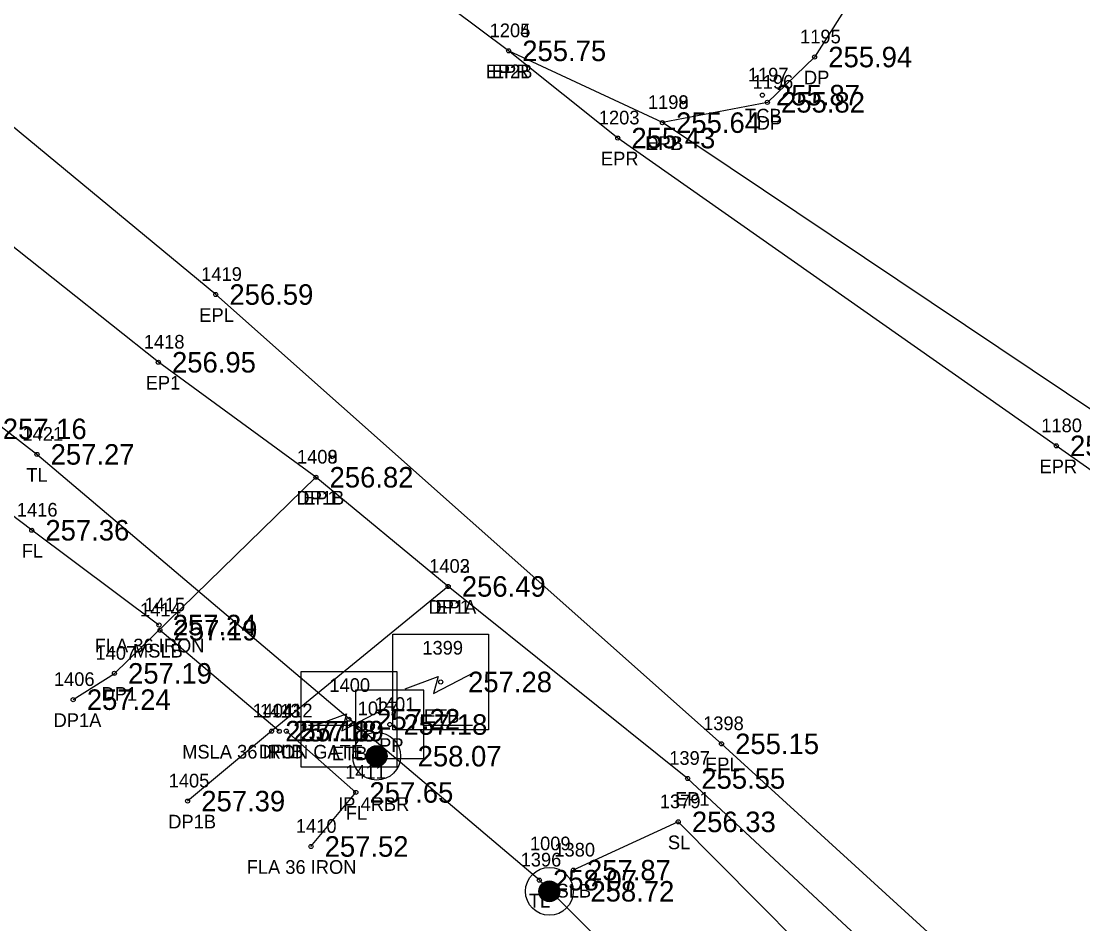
# Model space of a CAD drawing. Extents: x 1961231 to 1962574, y 799865 to 801120.
# Drawn here: x 1961948.3 to 1962025.9, y 800506.1 to 800572.1 of the extents above; entities that cross this region are included whole.
import ezdxf

# ---------------------------------------------------------------- set-up
doc = ezdxf.new("R2010")
doc.units = 0
for name, color, linetype in [('RD_EX_Conc_txCode', 7, 'Continuous'), ('RD_EX_Driveway', 7, 'Continuous'), ('RD_EX_Driveway_txCode', 7, 'Continuous'), ('RD_EX_DV_Prop_txCode', 7, 'Continuous'), ('RD_EX_DV_PropPin', 7, 'Continuous'), ('RD_EX_Fence_Other', 7, 'Continuous'), ('RD_EX_Fence_Other_txCode', 7, 'Continuous'), ('RD_EX_Misc', 7, 'Continuous'), ('RD_EX_Misc_txCode', 7, 'Continuous'), ('RD_EX_Road', 7, 'Continuous'), ('RD_EX_Road_txCode', 7, 'Continuous'), ('RD_EX_TX_Conc_ELEV', 7, 'Continuous'), ('RD_EX_TX_Driveway_ELEV', 7, 'Continuous'), ('RD_EX_TX_DV_Prop_ELEV', 7, 'Continuous'), ('RD_EX_TX_Fence_Other_ELEV', 7, 'Continuous'), ('RD_EX_TX_Misc_ELEV', 7, 'Continuous'), ('RD_EX_TX_Road_ELEV', 7, 'Continuous'), ('RD_EX_TX_UT_ELEV', 7, 'Continuous'), ('RD_EX_TX_VEG_ELEV', 7, 'Continuous'), ('RD_EX_UT', 7, 'Continuous'), ('RD_EX_UT_txCode', 7, 'Continuous'), ('RD_EX_VEG', 7, 'Continuous'), ('RD_EX_VEG_txCode', 7, 'Continuous'), ('RD_HC_Survey_ELEV', 7, 'Continuous'), ('RD_SMD_Locator', 7, 'Continuous')]:
    doc.layers.add(name, color=color, linetype=linetype)

msp = doc.modelspace()

# ---------------------------------------------------------------- linework, layer by layer
at = {"layer": 'RD_EX_Driveway'}
for points in [[(1962019.82, 800606.785), (1962009.296, 800574.262), (1962006.27, 800569.49), (1962002.818, 800566.176), (1961995.142, 800564.69)], [(1961952.05, 800522.48), (1961955.065, 800524.403), (1961969.799, 800538.748)], [(1961979.472, 800530.761), (1961966.56, 800520.176), (1961960.418, 800515.058)]]:
    msp.add_lwpolyline(points, dxfattribs=at)
at = {"layer": 'RD_EX_DV_PropPin'}
for p, q in [((1961973.61, 800517.917), (1961973.61, 800518.771)), ((1961973.645, 800517.87), (1961973.645, 800518.818)), ((1961973.68, 800517.829), (1961973.68, 800518.859)), ((1961973.715, 800517.793), (1961973.715, 800518.895)), ((1961973.75, 800517.762), (1961973.75, 800518.926)), ((1961973.785, 800517.734), (1961973.785, 800518.954)), ((1961973.82, 800517.709), (1961973.82, 800518.979)), ((1961973.855, 800517.688), (1961973.855, 800519)), ((1961973.89, 800517.668), (1961973.89, 800519.02)), ((1961973.925, 800517.651), (1961973.925, 800519.037)), ((1961973.96, 800517.636), (1961973.96, 800519.052)), ((1961973.995, 800517.624), (1961973.995, 800519.064)), ((1961974.03, 800517.613), (1961974.03, 800519.075)), ((1961974.065, 800517.603), (1961974.065, 800519.085)), ((1961974.1, 800517.596), (1961974.1, 800519.092)), ((1961974.135, 800517.59), (1961974.135, 800519.098)), ((1961974.17, 800517.586), (1961974.17, 800519.102)), ((1961974.205, 800517.584), (1961974.205, 800519.104)), ((1961974.24, 800517.583), (1961974.24, 800519.105)), ((1961974.275, 800517.584), (1961974.275, 800519.104)), ((1961974.311, 800517.586), (1961974.311, 800519.102)), ((1961974.346, 800517.59), (1961974.346, 800519.098)), ((1961974.381, 800517.596), (1961974.381, 800519.092)), ((1961974.416, 800517.603), (1961974.416, 800519.085)), ((1961974.451, 800517.613), (1961974.451, 800519.075)), ((1961974.486, 800517.624), (1961974.486, 800519.064)), ((1961974.521, 800517.636), (1961974.521, 800519.052)), ((1961974.556, 800517.651), (1961974.556, 800519.037)), ((1961974.591, 800517.668), (1961974.591, 800519.02)), ((1961974.626, 800517.688), (1961974.626, 800519)), ((1961974.661, 800517.709), (1961974.661, 800518.979)), ((1961974.696, 800517.734), (1961974.696, 800518.954)), ((1961974.731, 800517.762), (1961974.731, 800518.926)), ((1961974.766, 800517.793), (1961974.766, 800518.895)), ((1961974.801, 800517.829), (1961974.801, 800518.859)), ((1961974.836, 800517.87), (1961974.836, 800518.818)), ((1961974.871, 800517.917), (1961974.871, 800518.771)), ((1961973.505, 800518.148), (1961973.505, 800518.54)), ((1961973.54, 800518.046), (1961973.54, 800518.642)), ((1961973.575, 800517.974), (1961973.575, 800518.714)), ((1961974.906, 800517.974), (1961974.906, 800518.714)), ((1961974.941, 800518.046), (1961974.941, 800518.642)), ((1961974.976, 800518.148), (1961974.976, 800518.54)), ((1961986.139, 800508.263), (1961986.139, 800508.656)), ((1961986.174, 800508.162), (1961986.174, 800508.757)), ((1961986.21, 800508.09), (1961986.21, 800508.829)), ((1961986.245, 800508.033), (1961986.245, 800508.886)), ((1961986.28, 800507.985), (1961986.28, 800508.934)), ((1961986.315, 800507.944), (1961986.315, 800508.975)), ((1961986.35, 800507.909), (1961986.35, 800509.01)), ((1961986.385, 800507.877), (1961986.385, 800509.042)), ((1961986.42, 800507.85), (1961986.42, 800509.069)), ((1961986.455, 800507.825), (1961986.455, 800509.094)), ((1961986.49, 800507.803), (1961986.49, 800509.116)), ((1961986.525, 800507.784), (1961986.525, 800509.135)), ((1961986.56, 800507.767), (1961986.56, 800509.152)), ((1961986.595, 800507.752), (1961986.595, 800509.167)), ((1961986.63, 800507.739), (1961986.63, 800509.18)), ((1961986.665, 800507.728), (1961986.665, 800509.191)), ((1961986.7, 800507.719), (1961986.7, 800509.2)), ((1961986.735, 800507.711), (1961986.735, 800509.208)), ((1961986.77, 800507.706), (1961986.77, 800509.213)), ((1961986.805, 800507.702), (1961986.805, 800509.217)), ((1961986.84, 800507.699), (1961986.84, 800509.22)), ((1961986.875, 800507.698), (1961986.875, 800509.221)), ((1961986.91, 800507.699), (1961986.91, 800509.22)), ((1961986.945, 800507.702), (1961986.945, 800509.217)), ((1961986.98, 800507.706), (1961986.98, 800509.213)), ((1961987.015, 800507.711), (1961987.015, 800509.208)), ((1961987.05, 800507.719), (1961987.05, 800509.2)), ((1961987.085, 800507.728), (1961987.085, 800509.191)), ((1961987.12, 800507.739), (1961987.12, 800509.18)), ((1961987.155, 800507.752), (1961987.155, 800509.167)), ((1961987.19, 800507.767), (1961987.19, 800509.152)), ((1961987.225, 800507.784), (1961987.225, 800509.135)), ((1961987.26, 800507.803), (1961987.26, 800509.116)), ((1961987.295, 800507.825), (1961987.295, 800509.094)), ((1961987.33, 800507.85), (1961987.33, 800509.069)), ((1961987.365, 800507.877), (1961987.365, 800509.042)), ((1961987.4, 800507.909), (1961987.4, 800509.01)), ((1961987.435, 800507.944), (1961987.435, 800508.975)), ((1961987.47, 800507.985), (1961987.47, 800508.934)), ((1961987.505, 800508.033), (1961987.505, 800508.886)), ((1961987.54, 800508.09), (1961987.54, 800508.829)), ((1961987.575, 800508.162), (1961987.575, 800508.757)), ((1961987.61, 800508.263), (1961987.61, 800508.656))]:
    msp.add_line(p, q, dxfattribs=at)
for centre, radius in [((1961974.24, 800518.344), 1.75), ((1961974.24, 800518.344), 0.761), ((1961986.875, 800508.459), 1.75), ((1961986.875, 800508.459), 0.761)]:
    msp.add_circle(centre, radius, dxfattribs=at)
at = {"layer": 'RD_EX_Fence_Other'}
for points in [[(1961958.323, 800527.939), (1961949.019, 800534.872), (1961930.301, 800549.041)], [(1961969.438, 800511.738), (1961972.716, 800515.692), (1961967.641, 800520.178)]]:
    msp.add_lwpolyline(points, dxfattribs=at)
at = {"layer": 'RD_EX_Misc'}
msp.add_line((1961967.121, 800520.17), (1961958.392, 800527.563), dxfattribs=at)
at = {"layer": 'RD_EX_Road'}
for points in [[(1962276.74, 800366.531), (1962275.763, 800367.276), (1962226.463, 800400.661), (1962183.048, 800429.728), (1962145.981, 800455.375), (1962104.401, 800484.056), (1962056.773, 800517.941), (1962023.947, 800541.047), (1961991.873, 800563.562), (1961983.892, 800569.942), (1961938.772, 800603.672), (1961913.433, 800623.832), (1961897.726, 800636.174), (1961851.615, 800671.613), (1961815.859, 800699.483), (1961795.771, 800715.491), (1961771.879, 800733.735), (1961750.766, 800750.964), (1961735.626, 800762.821), (1961702.918, 800788.521)], [(1962241.795, 800315.68), (1962238.351, 800317.597), (1962189.917, 800352.695), (1962151.637, 800383.489), (1962113.782, 800416.386), (1962074.109, 800451.288), (1962034.784, 800486.956), (1962017.07, 800503.174), (1961999.461, 800519.248), (1961962.476, 800552.117), (1961937.077, 800573.106), (1961923.189, 800584.904), (1961883.072, 800617.432), (1961838.294, 800653.432), (1961801.423, 800682.572), (1961728.409, 800740.856), (1961722.948, 800745.107), (1961689.132, 800771.929)], [(1961992.53, 800418.336), (1962000.944, 800437), (1962011.011, 800464.808), (1962016.837, 800481.64), (1962015.313, 800499.647), (1961996.985, 800516.713), (1961979.472, 800530.761), (1961969.799, 800538.748), (1961958.277, 800547.161), (1961941.067, 800560.824), (1961925.414, 800573.413), (1961918.19, 800579.247), (1961879.318, 800611.179), (1961866.074, 800621.075), (1961838.294, 800653.432)], [(1962275.763, 800367.276), (1962274.032, 800371.184), (1962275.169, 800373.824), (1962239.929, 800394.942), (1962227.758, 800403.121), (1962207.726, 800416.444), (1962184.449, 800431.683), (1962152.889, 800453.775), (1962107.434, 800485.958), (1962091.521, 800497.238), (1962058.275, 800520.199), (1962027.136, 800543.255), (1961995.142, 800564.69), (1961983.892, 800569.942)]]:
    msp.add_lwpolyline(points, dxfattribs=at)
at = {"layer": 'RD_EX_UT'}
for p, q in [((1961977.694, 800523.169), (1961972.694, 800523.169)), ((1961972.694, 800523.169), (1961972.694, 800518.169)), ((1961977.694, 800518.169), (1961977.694, 800523.169)), ((1961969.263, 800520.606), (1961972.732, 800520.606)), ((1961977.622, 800520.606), (1961981.263, 800520.606)), ((1961972.694, 800518.169), (1961977.694, 800518.169))]:
    msp.add_line(p, q, dxfattribs=at)
for points in [[(1961975.431, 800520.275), (1961975.431, 800527.275), (1961982.431, 800527.275), (1961982.431, 800520.275)], [(1961968.711, 800517.545), (1961968.711, 800524.545), (1961975.711, 800524.545), (1961975.711, 800517.545)]]:
    msp.add_lwpolyline(points, close=True, dxfattribs=at)
for points in [[(1961976.33, 800523.269), (1961978.752, 800524.169), (1961978.406, 800522.923), (1961981.451, 800524.516)], [(1961969.609, 800520.539), (1961972.032, 800521.439), (1961971.686, 800520.193), (1961974.731, 800521.786)]]:
    msp.add_lwpolyline(points, dxfattribs=at)
at = {"layer": 'RD_EX_VEG'}
for points in [[(1961986.163, 800417.052), (1962008.727, 800486.692), (1961986.141, 800509.275), (1961949.4, 800540.421), (1961909.418, 800571.418), (1961867.438, 800598.729), (1961825.041, 800634.775), (1961788.236, 800662.233), (1961745.486, 800697.377)], [(1962007.192, 800493.608), (1962010.887, 800498.82), (1961996.296, 800513.539), (1961988.624, 800510.004)]]:
    msp.add_lwpolyline(points, dxfattribs=at)
at = {"layer": 'RD_SMD_Locator'}
for centre in [(1961983.892, 800569.942), (1961983.892, 800569.942), (1962006.27, 800569.49), (1962002.451, 800566.703), (1962002.818, 800566.176), (1961995.142, 800564.69), (1961995.142, 800564.69), (1961991.873, 800563.562), (1961962.476, 800552.117), (1961958.277, 800547.161), (1961949.4, 800540.421), (1962023.947, 800541.047), (1961969.799, 800538.748), (1961969.799, 800538.748), (1961949.019, 800534.872), (1961979.472, 800530.761), (1961979.472, 800530.761), (1961958.323, 800527.939), (1961958.392, 800527.563), (1961955.065, 800524.403), (1961978.931, 800523.775), (1961952.05, 800522.48), (1961972.211, 800521.045), (1961966.56, 800520.176), (1961967.121, 800520.17), (1961967.641, 800520.178), (1961975.203, 800520.66), (1961999.461, 800519.248), (1961974.241, 800518.344), (1961996.985, 800516.713), (1961972.716, 800515.692), (1961960.418, 800515.058), (1961996.296, 800513.539), (1961969.438, 800511.738), (1961988.624, 800510.004), (1961986.141, 800509.275), (1961986.875, 800508.459)]:
    msp.add_circle(centre, 0.15, dxfattribs=at)

# ---------------------------------------------------------------- texts
at = {"layer": 'RD_EX_Conc_txCode'}
for s, p in [('1197', (1962001.388, 800567.703)), ('TCB', (1962001.184, 800564.703))]:
    msp.add_text(s, height=1, dxfattribs=at).set_placement(p)
at = {"layer": 'RD_EX_Driveway_txCode'}
for s, p in [('1195', (1962005.207, 800570.49)), ('DP', (1962005.491, 800567.49)), ('1196', (1962001.732, 800567.176)), ('1198', (1961994.079, 800565.69)), ('DP', (1962002.039, 800564.176)), ('DPB', (1961993.89, 800562.69)), ('1408', (1961968.413, 800539.748)), ('DP1B', (1961968.381, 800536.748)), ('1403', (1961978.086, 800531.761)), ('DP1A', (1961978.039, 800528.761)), ('1407', (1961953.679, 800525.403)), ('1406', (1961950.64, 800523.48)), ('DP1', (1961954.12, 800522.403)), ('1404', (1961965.174, 800521.176)), ('DP1A', (1961950.617, 800520.48)), ('DP1', (1961965.615, 800518.176)), ('1405', (1961959.032, 800516.058)), ('DP1B', (1961959.001, 800513.058))]:
    msp.add_text(s, height=1, dxfattribs=at).set_placement(p)
at = {"layer": 'RD_EX_DV_Prop_txCode'}
for s, p in [('1027', (1961972.855, 800521.344)), ('IP 4RBR', (1961971.429, 800514.344)), ('1009', (1961985.45, 800511.46))]:
    msp.add_text(s, height=1, dxfattribs=at).set_placement(p)
at = {"layer": 'RD_EX_Fence_Other_txCode'}
for s, p in [('1416', (1961947.932, 800535.872)), ('FL', (1961948.287, 800532.872)), ('1415', (1961957.26, 800528.939)), ('FLA 36 IRON', (1961953.622, 800525.939)), ('1412', (1961966.578, 800521.178)), ('FLB', (1961966.436, 800518.178)), ('1411', (1961971.936, 800516.692)), ('FL', (1961971.984, 800513.692)), ('1410', (1961968.335, 800512.738)), ('FLA 36 IRON', (1961964.737, 800509.738))]:
    msp.add_text(s, height=1, dxfattribs=at).set_placement(p)
at = {"layer": 'RD_EX_Misc_txCode'}
for s, p in [('1414', (1961956.94, 800528.563)), ('MSLB', (1961956.422, 800525.563)), ('1413', (1961965.705, 800521.17)), ('MSLA 36 IRON GATE', (1961960.021, 800518.17))]:
    msp.add_text(s, height=1, dxfattribs=at).set_placement(p)
at = {"layer": 'RD_EX_Road_txCode'}
for s, p in [('1204', (1961982.506, 800570.942)), ('1205', (1961982.506, 800570.942)), ('EP2B', (1961982.215, 800567.942)), ('EPR', (1961982.663, 800567.942)), ('1199', (1961994.079, 800565.69)), ('1203', (1961990.487, 800564.562)), ('EP2', (1961993.937, 800562.69)), ('EPR', (1961990.645, 800561.562)), ('1419', (1961961.413, 800553.117)), ('EPL', (1961961.272, 800550.117)), ('1418', (1961957.214, 800548.161)), ('EP1', (1961957.356, 800545.161)), ('1180', (1962022.845, 800542.047)), ('1409', (1961968.413, 800539.748)), ('EPR', (1962022.719, 800539.047)), ('EP1', (1961968.877, 800536.748)), ('1402', (1961978.086, 800531.761)), ('EP1', (1961978.551, 800528.761)), ('1398', (1961998.114, 800520.248)), ('1397', (1961995.639, 800517.713)), ('EPL', (1961998.256, 800517.248)), ('EP1', (1961996.064, 800514.713))]:
    msp.add_text(s, height=1, dxfattribs=at).set_placement(p)
at = {"layer": 'RD_EX_TX_Conc_ELEV'}
msp.add_text('255.87', height=1.5, dxfattribs=at).set_placement((1962003.451, 800565.953))
at = {"layer": 'RD_EX_TX_Driveway_ELEV'}
for s, p in [('255.94', (1962007.27, 800568.74)), ('255.82', (1962003.818, 800565.426)), ('255.64', (1961996.142, 800563.94)), ('256.82', (1961970.799, 800537.998)), ('256.49', (1961980.472, 800530.011)), ('257.19', (1961956.065, 800523.653)), ('257.24', (1961953.05, 800521.73)), ('257.18', (1961967.56, 800519.426)), ('257.39', (1961961.418, 800514.308))]:
    msp.add_text(s, height=1.5, dxfattribs=at).set_placement(p)
at = {"layer": 'RD_EX_TX_DV_Prop_ELEV'}
for s, p in [('258.07', (1961977.241, 800517.594)), ('258.72', (1961989.875, 800507.71))]:
    msp.add_text(s, height=1.5, dxfattribs=at).set_placement(p)
at = {"layer": 'RD_EX_TX_Fence_Other_ELEV'}
for s, p in [('257.36', (1961950.019, 800534.122)), ('257.24', (1961959.323, 800527.189)), ('257.19', (1961968.641, 800519.428)), ('257.65', (1961973.716, 800514.942)), ('257.52', (1961970.438, 800510.988))]:
    msp.add_text(s, height=1.5, dxfattribs=at).set_placement(p)
at = {"layer": 'RD_EX_TX_Misc_ELEV'}
for s, p in [('257.19', (1961959.392, 800526.813)), ('257.18', (1961968.121, 800519.42))]:
    msp.add_text(s, height=1.5, dxfattribs=at).set_placement(p)
at = {"layer": 'RD_EX_TX_Road_ELEV'}
for s, p in [('255.75', (1961984.892, 800569.192)), ('255.75', (1961984.892, 800569.192)), ('255.64', (1961996.142, 800563.94)), ('255.43', (1961992.873, 800562.812)), ('256.59', (1961963.476, 800551.367)), ('256.95', (1961959.277, 800546.411)), ('254.07', (1962024.947, 800540.297)), ('256.82', (1961970.799, 800537.998)), ('256.49', (1961980.472, 800530.011)), ('255.15', (1962000.461, 800518.498)), ('255.55', (1961997.985, 800515.963))]:
    msp.add_text(s, height=1.5, dxfattribs=at).set_placement(p)
at = {"layer": 'RD_EX_TX_UT_ELEV'}
for s, p in [('257.16', (1961946.903, 800541.539)), ('257.28', (1961980.931, 800523.025)), ('257.22', (1961974.211, 800520.295))]:
    msp.add_text(s, height=1.5, dxfattribs=at).set_placement(p)
at = {"layer": 'RD_EX_TX_VEG_ELEV'}
for s, p in [('257.27', (1961950.4, 800539.671)), ('256.33', (1961997.296, 800512.789)), ('257.87', (1961989.624, 800509.254)), ('258.07', (1961987.141, 800508.525))]:
    msp.add_text(s, height=1.5, dxfattribs=at).set_placement(p)
at = {"layer": 'RD_EX_UT_txCode'}
for s, p in [('1399', (1961977.585, 800525.775)), ('1400', (1961970.786, 800523.045)), ('1401', (1961974.101, 800521.66)), ('ETB', (1961977.687, 800520.775)), ('PP', (1961974.423, 800518.66)), ('ETB', (1961970.967, 800518.045))]:
    msp.add_text(s, height=1, dxfattribs=at).set_placement(p)
at = {"layer": 'RD_EX_VEG_txCode'}
for s, p in [('1421', (1961948.337, 800541.421)), ('TL', (1961948.629, 800538.421)), ('1379', (1961994.95, 800514.539)), ('SL', (1961995.54, 800511.539)), ('1380', (1961987.238, 800511.004)), ('1396', (1961984.771, 800510.275)), ('SLB', (1961987.396, 800508.004)), ('TL', (1961985.37, 800507.275))]:
    msp.add_text(s, height=1, dxfattribs=at).set_placement(p)
at = {"layer": 'RD_HC_Survey_ELEV'}
msp.add_text('257.18', height=1.5, dxfattribs=at).set_placement((1961976.203, 800519.91))

doc.saveas('drawing.dxf')
